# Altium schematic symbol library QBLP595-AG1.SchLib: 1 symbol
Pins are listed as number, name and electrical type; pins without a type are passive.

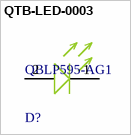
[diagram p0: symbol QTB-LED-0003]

## QTB-LED-0003
designator D?, comment QBLP595-AG1
LED YELLOW/GREEN CLEAR 0402 SMD; Manufacturer: QT Brightek (QTB); Test Current: 20mA; Lens Size: 0.5mm; Forward Voltage: 2.0V; Lens Style: Flat; Luminous Intensity: 35mcd; Lens Color: Colorless; Viewing Angle: 140°; Dominant Wavelength: 570nm
footprint FP-QBLP595-AG-MFG
pins: 1 CATHODE (-), 2 ANODE (+)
